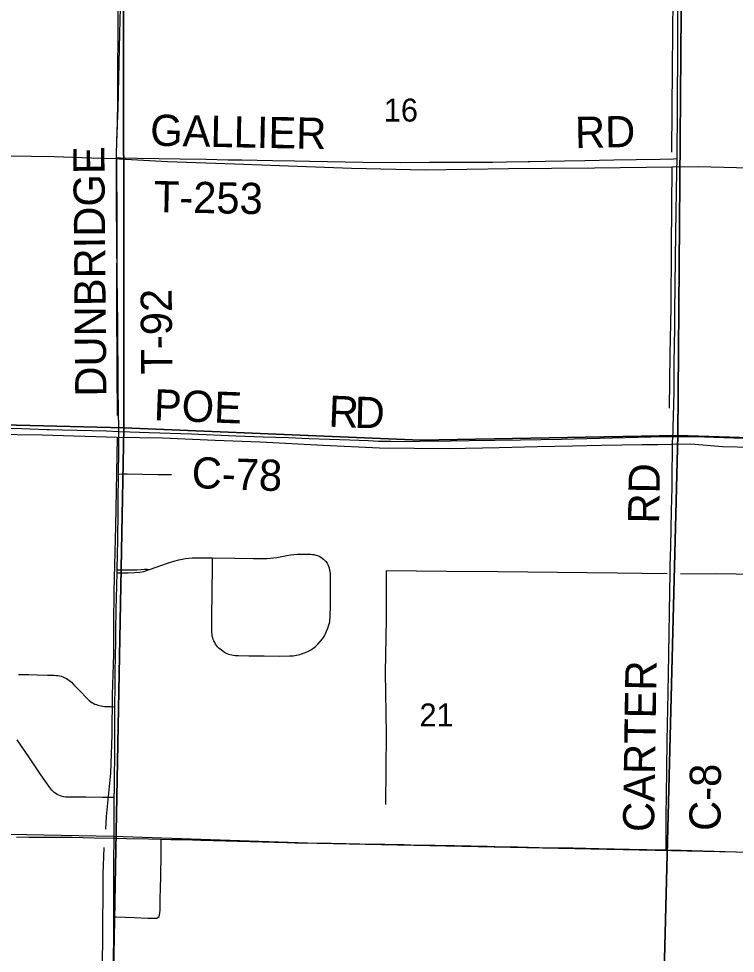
# Model space of a CAD drawing. Extents: x -59 to 43, y 0 to 22.
# Drawn here: x 27.1 to 28.407, y 17.288 to 18.99 of the extents above; entities that cross this region are included whole.
import ezdxf

# ---------------------------------------------------------------- set-up
doc = ezdxf.new("R2010")
doc.units = 0
for name, color, linetype in [('GM_X_City_Street', 7, 'Continuous'), ('GM_X_County_Road', 7, 'Continuous'), ('GM_X_County_Road_Text', 7, 'Continuous'), ('GM_X_Minor_River', 7, 'Continuous'), ('GM_X_Rail_Line', 7, 'Continuous'), ('GM_X_Section', 7, 'Continuous'), ('GM_X_Section_Text', 7, 'Continuous'), ('GM_X_State_Route', 7, 'Continuous'), ('GM_X_Township_Road', 7, 'Continuous'), ('GM_X_Township_Road_Text', 7, 'Continuous')]:
    doc.layers.add(name, color=color, linetype=linetype)

msp = doc.modelspace()

# ---------------------------------------------------------------- linework, layer by layer
at = {"layer": 'GM_X_City_Street'}
msp.add_line((27.3381, 17.9869), (27.339, 17.9873), dxfattribs=at)
for points in [[(27.2824, 18.1609), (27.2919, 18.161), (27.2981, 18.161), (27.3541, 18.1602), (27.379, 18.1601)], [(27.339, 17.9873), (27.3507, 17.9914), (27.3713, 17.9984), (27.3831, 18.0021), (27.3921, 18.0046), (27.3982, 18.0059), (27.4043, 18.007), (27.4105, 18.0078), (27.4167, 18.0083), (27.4224, 18.0084), (27.4291, 18.0085), (27.4359, 18.0085), (27.4508, 18.0084), (27.4537, 18.0083), (27.4942, 18.0078), (27.5282, 18.0072), (27.5437, 18.007), (27.5529, 18.0071), (27.559, 18.0075), (27.5652, 18.0081), (27.5712, 18.009), (27.5803, 18.0108), (27.5894, 18.0126), (27.5956, 18.0137), (27.6017, 18.0144), (27.608, 18.0149), (27.6173, 18.0152), (27.6297, 18.015), (27.6328, 18.0149), (27.636, 18.0146), (27.6391, 18.0141), (27.6422, 18.0134), (27.6452, 18.0124), (27.6481, 18.0111), (27.6509, 18.0096), (27.6535, 18.0078), (27.656, 18.0058), (27.6583, 18.0036), (27.6604, 18.0013), (27.6624, 17.9987), (27.6645, 17.9951)], [(27.4751, 17.8363), (27.4724, 17.838), (27.4699, 17.8399), (27.4675, 17.8419), (27.4652, 17.844), (27.463, 17.8463), (27.461, 17.8487), (27.4591, 17.8513), (27.4576, 17.854), (27.4562, 17.8568), (27.455, 17.8597), (27.4541, 17.8627), (27.4533, 17.8658), (27.4528, 17.8689), (27.4525, 17.872), (27.4523, 17.8751), (27.4523, 17.8814), (27.4524, 17.8906), (27.4525, 17.906), (27.4528, 17.9399), (27.4536, 17.9984), (27.4537, 18.0083)], [(27.6329, 17.8407), (27.6364, 17.8429), (27.6389, 17.8448), (27.6414, 17.8468), (27.6437, 17.8489), (27.6459, 17.8512), (27.6501, 17.8559), (27.654, 17.8608), (27.6558, 17.8634), (27.6575, 17.8661), (27.659, 17.8688), (27.6604, 17.8717), (27.6617, 17.8745), (27.664, 17.8804), (27.6659, 17.8864), (27.6667, 17.8894), (27.6673, 17.8925), (27.6678, 17.8957), (27.6681, 17.8988), (27.6684, 17.9051), (27.6687, 17.9175), (27.6686, 17.9518), (27.669, 17.9705), (27.6689, 17.9767), (27.6687, 17.9799), (27.6684, 17.983), (27.6678, 17.9862), (27.667, 17.9892), (27.6659, 17.9922), (27.6645, 17.9951)], [(27.2798, 17.9809), (27.3001, 17.9812), (27.3123, 17.9816), (27.3214, 17.9823), (27.3278, 17.9834), (27.3324, 17.9846), (27.3353, 17.9857), (27.3381, 17.9869)], [(27.2799, 17.9866), (27.2918, 17.9863), (27.2974, 17.9862), (27.3071, 17.9865), (27.3155, 17.9867), (27.3234, 17.9871), (27.3294, 17.9875), (27.335, 17.9876), (27.339, 17.9873)], [(27.4751, 17.8363), (27.4796, 17.8342), (27.4826, 17.8331), (27.4886, 17.8314), (27.4917, 17.8309), (27.4949, 17.8305), (27.5011, 17.8302), (27.5197, 17.83), (27.5476, 17.8296), (27.5755, 17.8293), (27.5942, 17.8295), (27.6004, 17.8299), (27.6035, 17.8302), (27.6066, 17.8308), (27.6097, 17.8314), (27.6127, 17.8322), (27.6157, 17.8332), (27.6216, 17.8353), (27.6273, 17.8379), (27.6329, 17.8407)], [(27.1002, 17.7958), (27.1188, 17.7955), (27.1343, 17.7951), (27.1528, 17.7946), (27.1652, 17.7943), (27.1683, 17.7941), (27.1715, 17.7938), (27.1746, 17.7932), (27.1776, 17.7925), (27.1806, 17.7914), (27.1835, 17.7902), (27.1864, 17.7888), (27.1891, 17.7873), (27.1917, 17.7855), (27.1942, 17.7836), (27.1966, 17.7815), (27.201, 17.7771), (27.2117, 17.766), (27.2245, 17.7525), (27.2267, 17.7504), (27.2289, 17.7484), (27.2313, 17.7465), (27.2338, 17.7448), (27.2364, 17.7433), (27.2392, 17.742), (27.242, 17.7409), (27.2449, 17.7399), (27.2478, 17.7391), (27.2508, 17.7385), (27.2538, 17.738), (27.2568, 17.7377), (27.2629, 17.7374), (27.2691, 17.7372), (27.2756, 17.737)], [(27.2746, 17.5719), (27.2663, 17.5719), (27.2539, 17.5719), (27.2229, 17.5721), (27.2074, 17.5722), (27.1888, 17.5724), (27.1856, 17.5726), (27.1825, 17.573), (27.1794, 17.5736), (27.1763, 17.5745), (27.1734, 17.5757), (27.1705, 17.5771), (27.1678, 17.5788), (27.1653, 17.5807), (27.1629, 17.5828), (27.1607, 17.5851), (27.1587, 17.5875), (27.155, 17.5926), (27.141, 17.613), (27.1202, 17.6439), (27.0974, 17.677)], [(27.2737, 17.3545), (27.2782, 17.3543), (27.3111, 17.3532), (27.3359, 17.3522), (27.3452, 17.3517), (27.3483, 17.3517), (27.3514, 17.3519), (27.3528, 17.3522), (27.3542, 17.3531), (27.3562, 17.3552), (27.3573, 17.358), (27.3578, 17.3611), (27.3581, 17.3674), (27.3585, 17.3922), (27.3587, 17.4015), (27.3598, 17.4634), (27.3599, 17.4735), (27.36, 17.4851), (27.36, 17.4958)]]:
    msp.add_lwpolyline(points, dxfattribs=at)
at = {"layer": 'GM_X_County_Road'}
for p, q in [((27.2831, 18.2383), (27.3031, 18.2378)), ((27.7564, 18.2209), (27.7756, 18.2206))]:
    msp.add_line(p, q, dxfattribs=at)
for points in [[(28.3005, 18.7354), (28.3005, 18.7384), (28.3011, 18.8255), (28.3019, 18.9436), (28.302, 18.9933), (28.3022, 19.0107), (28.3029, 19.1189), (28.3034, 19.1724), (28.3043, 19.2315)], [(28.2926, 18.2293), (28.2932, 18.2368), (28.2937, 18.2467), (28.2943, 18.266), (28.295, 18.3113), (28.2955, 18.3617), (28.2965, 18.4276), (28.2967, 18.4562), (28.2985, 18.6004), (28.3002, 18.7117), (28.3005, 18.7354)], [(26.9636, 18.2474), (26.9739, 18.247), (26.9949, 18.2465), (27.0247, 18.2457), (27.0681, 18.2447), (27.1053, 18.2436), (27.1519, 18.2423), (27.156, 18.2422)], [(27.156, 18.2422), (27.1798, 18.2416), (27.2605, 18.2395), (27.2831, 18.2383)], [(27.3031, 18.2378), (27.338, 18.2367), (27.4156, 18.2339), (27.4963, 18.2307), (27.5459, 18.2288), (27.5924, 18.2272), (27.6296, 18.2257), (27.6669, 18.2243), (27.7041, 18.223), (27.7382, 18.2217), (27.7564, 18.2209)], [(27.7756, 18.2206), (27.7786, 18.2205), (27.8035, 18.2202), (27.8315, 18.2205), (27.8875, 18.2211), (27.9217, 18.2218), (27.9683, 18.2223), (28.015, 18.2229), (28.0896, 18.2246), (28.1362, 18.2257), (28.2761, 18.2291), (28.2926, 18.2293)], [(28.288, 17.9791), (28.2882, 17.995), (28.2889, 18.028), (28.2904, 18.0945), (28.2913, 18.1355), (28.2916, 18.1647), (28.2919, 18.2001), (28.292, 18.2194), (28.2925, 18.2275), (28.2926, 18.2293)], [(28.2926, 18.2293), (28.3041, 18.2294), (28.3289, 18.2293), (28.3507, 18.2288), (28.5278, 18.2227), (28.6086, 18.2199), (28.6708, 18.2176), (28.7453, 18.2141), (28.7919, 18.2122), (28.8324, 18.2109), (28.8728, 18.2101), (28.9412, 18.2087), (29.0531, 18.2062), (29.1339, 18.2047), (29.2116, 18.2024), (29.28, 18.2), (29.2977, 18.1995), (29.3018, 18.1994), (29.3086, 18.1992)], [(28.2804, 17.4762), (28.2804, 17.4807), (28.2806, 17.4996), (28.2809, 17.5194), (28.2808, 17.5406), (28.2815, 17.5748), (28.2819, 17.6233), (28.2826, 17.6749), (28.2842, 17.7625), (28.2853, 17.8328), (28.2875, 17.9471), (28.288, 17.9791)]]:
    msp.add_lwpolyline(points, dxfattribs=at)
at = {"layer": 'GM_X_Minor_River'}
for points in [[(28.3063, 20.9), (28.3063, 20.8142), (28.3047, 20.6511), (28.3041, 20.4424), (28.3053, 20.218), (28.3023, 19.9234), (28.2994, 19.7566), (28.2991, 19.5715), (28.2973, 19.4803), (28.2956, 19.3161), (28.2947, 19.2172), (28.2918, 18.901), (28.2905, 18.747)], [(27.2943, 20.5775), (27.296, 20.2192), (27.2947, 20.0523), (27.2939, 19.9721), (27.2909, 19.7174), (27.288, 19.4981), (27.2854, 19.3781), (27.284, 19.2766), (27.2833, 19.2245), (27.2809, 19.0196), (27.2803, 18.8364), (27.2792, 18.7725)], [(29.2875, 18.7036), (28.9988, 18.7085), (28.858, 18.7106), (28.712, 18.7152), (28.5732, 18.7176), (28.432, 18.7179), (28.3387, 18.7202), (28.2912, 18.7196), (28.15, 18.7183), (27.9931, 18.7167), (27.8416, 18.7142), (27.7069, 18.7173), (27.4938, 18.7253), (27.3714, 18.7296), (27.284, 18.7343), (27.2789, 18.7349), (27.25, 18.7354), (27.1651, 18.7386), (27.0399, 18.7402)], [(27.2789, 18.7349), (27.2793, 18.6163), (27.2787, 18.4745), (27.2793, 18.3475), (27.2797, 18.2676)], [(28.2912, 18.7196), (28.2897, 18.5748), (28.2892, 18.4642), (28.2876, 18.379), (28.2859, 18.2806)], [(28.4376, 18.2093), (28.3834, 18.2105), (28.3254, 18.2152), (28.2901, 18.2147), (28.2654, 18.2139), (28.2366, 18.214), (28.1629, 18.213), (28.1097, 18.2115), (28.0456, 18.2103), (27.976, 18.2085), (27.8845, 18.2069), (27.7581, 18.2083), (27.6554, 18.2131), (27.5406, 18.2187), (27.4583, 18.2218), (27.3627, 18.2261), (27.2796, 18.2273), (27.1431, 18.2316), (27.0505, 18.2327)], [(27.2796, 18.2273), (27.277, 18.0658), (27.2736, 17.9476), (27.2734, 17.8868), (27.273, 17.8324), (27.2709, 17.7591), (27.2703, 17.6861), (27.2676, 17.6162), (27.2596, 17.5372)], [(28.2823, 17.9792), (28.1916, 17.9803), (28.0827, 17.9815), (27.9746, 17.9827), (27.8808, 17.9831), (27.7704, 17.9847), (27.7701, 17.8958), (27.7685, 17.7992), (27.7703, 17.6878), (27.7693, 17.5589)], [(29.1285, 17.9421), (29.082, 17.9506), (29.0447, 17.8919), (29.0068, 17.9067), (28.9602, 17.9233), (28.92, 17.9389), (28.8763, 17.9508), (28.829, 17.9567), (28.7551, 17.9611), (28.682, 17.9674), (28.5714, 17.9747), (28.4792, 17.977), (28.3723, 17.9793), (28.3066, 17.9785)], [(27.2596, 17.5372), (27.2584, 17.514)], [(27.8422, 16.6105), (27.7565, 16.6644), (27.6726, 16.7119), (27.6644, 16.7181), (27.6546, 16.7225), (27.647, 16.7245), (27.6368, 16.7258), (27.6265, 16.7264), (27.5445, 16.729), (27.4441, 16.7289), (27.3221, 16.7277), (27.2374, 16.7273), (27.2358, 16.7433), (27.2358, 16.7657), (27.2391, 16.8891), (27.2437, 16.9923), (27.2493, 17.1339), (27.2539, 17.3056), (27.2546, 17.4328), (27.2563, 17.4806)]]:
    msp.add_lwpolyline(points, dxfattribs=at)
at = {"layer": 'GM_X_Rail_Line'}
msp.add_lwpolyline([(26.5111, 17.5161), (27.2733, 17.5012), (27.6443, 17.4884), (28.6422, 17.4679)], dxfattribs=at)
at = {"layer": 'GM_X_Section'}
for points in [[(26.283, 19.2582), (27.2913, 19.2374), (27.2918, 18.2449), (26.2659, 18.2705), (26.2571, 18.8106)], [(27.2913, 19.2374), (28.3099, 19.2353), (28.3019, 18.2312), (27.8326, 18.2227), (27.2918, 18.2449)], [(28.3099, 19.2353), (29.3087, 19.2244), (29.309, 19.2191), (29.2974, 18.199), (28.3019, 18.2312)], [(26.2659, 18.2705), (27.2918, 18.2449), (27.273, 17.253), (26.2782, 17.275)], [(28.3019, 18.2312), (28.2762, 17.2295), (27.273, 17.253), (27.2918, 18.2449), (27.8326, 18.2227)], [(28.3019, 18.2312), (29.2974, 18.199), (29.2824, 17.2037), (28.2762, 17.2295)]]:
    msp.add_lwpolyline(points, close=True, dxfattribs=at)
at = {"layer": 'GM_X_State_Route'}
for p, q in [((27.0961, 17.4999), (27.1189, 17.4997)), ((27.5223, 17.4916), (27.5892, 17.4896)), ((27.5892, 17.4896), (27.6041, 17.4892))]:
    msp.add_line(p, q, dxfattribs=at)
for points in [[(27.1189, 17.4997), (27.1441, 17.4996), (27.1668, 17.4994), (27.1907, 17.4992)], [(27.1907, 17.4992), (27.1977, 17.4992), (27.238, 17.4984), (27.2741, 17.4977), (27.2748, 17.4976), (27.28, 17.4975), (27.2968, 17.4972), (27.3371, 17.4963), (27.36, 17.4958), (27.3774, 17.4955), (27.4021, 17.4951), (27.4324, 17.4943), (27.5223, 17.4916)], [(27.6041, 17.4892), (27.6088, 17.4894), (27.6708, 17.4883), (27.7483, 17.4868), (27.768, 17.4867)], [(27.768, 17.4867), (27.8033, 17.4861), (27.8282, 17.4852), (27.8442, 17.485), (27.8452, 17.485), (27.8593, 17.4848), (27.8899, 17.4842)], [(27.8899, 17.4842), (27.8909, 17.4842), (27.895, 17.4841), (27.9542, 17.4829)], [(27.9542, 17.4829), (27.9683, 17.4826), (28.0103, 17.4817), (28.0492, 17.4809), (28.1111, 17.4798), (28.1581, 17.479), (28.2136, 17.4777), (28.2778, 17.4763), (28.2804, 17.4762), (28.3075, 17.4756), (28.3884, 17.4731), (28.4475, 17.4715), (28.4973, 17.4698), (28.5347, 17.4687), (28.5906, 17.4671), (28.6342, 17.4659), (28.6872, 17.4645), (28.7369, 17.4631), (28.7653, 17.4622), (28.7843, 17.4617), (28.796, 17.4613), (28.824, 17.4606), (28.8614, 17.4597), (28.875, 17.4595)]]:
    msp.add_lwpolyline(points, dxfattribs=at)
at = {"layer": 'GM_X_Township_Road'}
msp.add_line((27.2831, 18.2383), (27.2829, 18.2465), dxfattribs=at)
for points in [[(27.2788, 18.737), (27.2789, 18.7447), (27.28, 18.7857), (27.2815, 18.8267), (27.2822, 18.8553), (27.2834, 18.9094), (27.2847, 18.9641), (27.2859, 19.01), (27.2875, 19.0722), (27.2884, 19.1219), (27.2897, 19.1791), (27.2908, 19.2201), (27.2911, 19.2348)], [(27.2829, 18.2465), (27.2824, 18.2729), (27.2819, 18.3201), (27.2808, 18.4333), (27.2802, 18.478), (27.28, 18.5191), (27.2794, 18.5874), (27.2785, 18.6539), (27.2784, 18.7031), (27.2788, 18.737)], [(27.2788, 18.737), (27.2859, 18.7369), (27.317, 18.7362), (27.3948, 18.735), (27.4415, 18.7343), (27.482, 18.7335), (27.5069, 18.733), (27.5629, 18.7322), (27.6033, 18.7313), (27.6313, 18.7306), (27.7278, 18.729), (27.7963, 18.7286), (27.8492, 18.7288), (27.8928, 18.729), (27.9208, 18.7291), (27.9644, 18.7291), (27.9893, 18.7295), (28.0289, 18.7303)], [(28.0289, 18.7303), (28.0329, 18.7304), (28.0609, 18.7309), (28.0951, 18.7316), (28.1325, 18.7321), (28.1854, 18.733), (28.2258, 18.734), (28.2694, 18.7347), (28.2943, 18.7353), (28.3005, 18.7354)], [(27.2824, 18.1609), (27.2831, 18.2033), (27.283, 18.2174), (27.2831, 18.2383)], [(27.2798, 17.9809), (27.2799, 17.9866), (27.2801, 17.9959), (27.2803, 18.0053), (27.2812, 18.0488), (27.2816, 18.0868), (27.2819, 18.1168), (27.2822, 18.1538), (27.2824, 18.1609)], [(27.2746, 17.5719), (27.2748, 17.587), (27.2753, 17.6706), (27.2753, 17.7016), (27.2756, 17.737), (27.276, 17.7758), (27.2762, 17.8008), (27.2772, 17.8565), (27.2774, 17.8752), (27.2779, 17.9154), (27.2784, 17.9347), (27.2798, 17.9809)], [(27.2741, 17.4977), (27.2741, 17.5093), (27.2742, 17.5214), (27.2743, 17.5374), (27.2746, 17.5719)], [(27.2737, 17.3545), (27.2735, 17.4061), (27.2738, 17.4561), (27.2741, 17.4977)], [(27.2657, 17.0349), (27.2678, 17.0901), (27.2713, 17.2017), (27.2725, 17.2326), (27.273, 17.2543), (27.2732, 17.2792), (27.2735, 17.3163), (27.2737, 17.3545)]]:
    msp.add_lwpolyline(points, dxfattribs=at)

# ---------------------------------------------------------------- texts
at = {"layer": 'GM_X_County_Road_Text'}
for s, height, rotation, p in [('POE', 0.05682, 357.8126, (27.3459, 18.2589)), ('R', 0.0568, 357.5013, (27.6644, 18.2473)), ('D', 0.0568, 358.5893, (27.7122, 18.2452)), ('C-78', 0.05682, 357.9421, (27.415, 18.1355)), ('RD', 0.05682, 89.0267, (28.2677, 18.0703)), ('CARTER', 0.05682, 89.1265, (28.2585, 17.5085)), ('C-8', 0.05682, 89.5522, (28.3796, 17.5106))]:
    msp.add_text(s, height=height, rotation=rotation, dxfattribs=at).set_placement(p)
at = {"layer": 'GM_X_Section_Text'}
for s, p in [('16', (27.7659, 18.8029)), ('21', (27.8309, 17.7011))]:
    msp.add_text(s, height=0.04186, rotation=0, dxfattribs=at).set_placement(p)
at = {"layer": 'GM_X_Township_Road_Text'}
for s, rotation, p in [('GALLIER', 358.8783, (27.3397, 18.759)), ('RD', 0.987, (28.1149, 18.7548)), ('DUNBRIDGE', 90.4654, (27.2602, 18.3021)), ('T-253', 358.8814, (27.3463, 18.638)), ('T-92', 90.3535, (27.3803, 18.3422))]:
    msp.add_text(s, height=0.05682, rotation=rotation, dxfattribs=at).set_placement(p)

doc.saveas('drawing.dxf')
